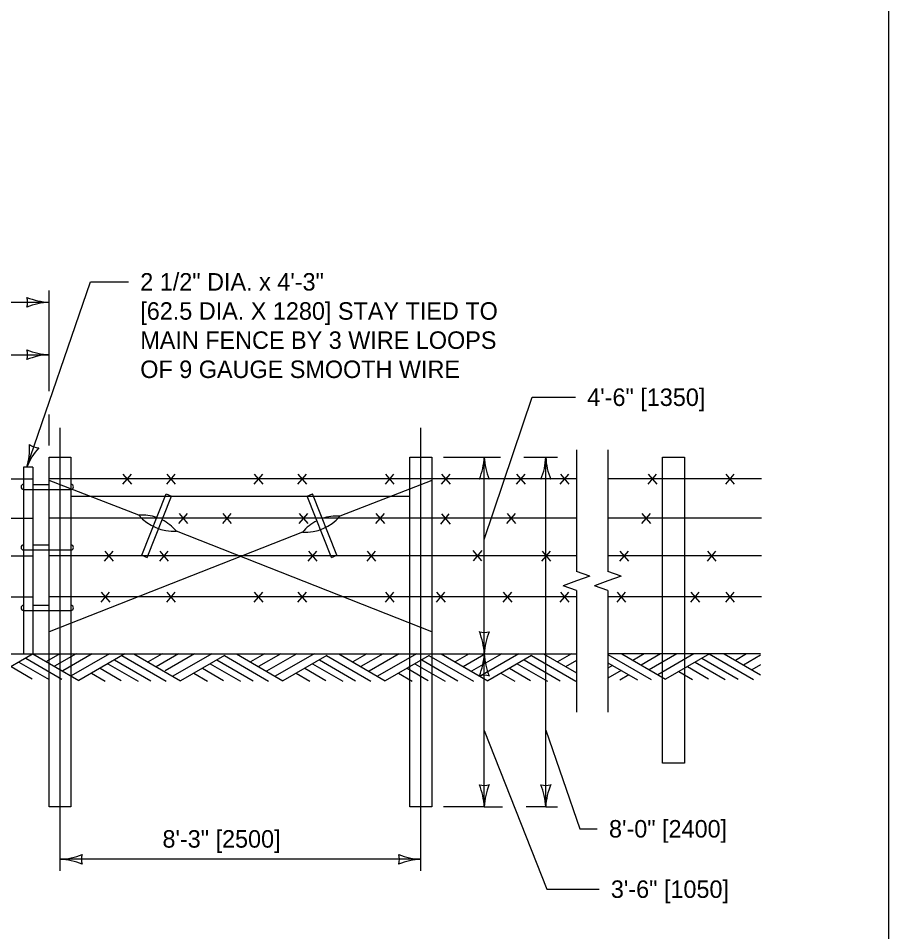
# Model space of a CAD drawing. Extents: x 49991.4 to 50021, y 49987.6 to 50011.4.
# Drawn here: x 50005.629 to 50008.615, y 50005.124 to 50008.258 of the extents above; entities that cross this region are included whole.
import ezdxf

# ---------------------------------------------------------------- set-up
doc = ezdxf.new("R2010")
doc.units = 0
for name, color, linetype in [('Level 1', 7, 'Continuous'), ('Level 2', 7, 'Continuous'), ('Level 3', 7, 'Continuous'), ('Level 4', 7, 'Continuous'), ('Level 5', 7, 'Continuous'), ('Level 6', 7, 'Continuous')]:
    doc.layers.add(name, color=color, linetype=linetype)

msp = doc.modelspace()

# ---------------------------------------------------------------- linework, layer by layer
at = {"layer": 'Level 1'}
for p, q in [((50005.7349, 50006.7523), (50005.8099, 50006.7523)), ((50005.7349, 50006.0773), (50005.7349, 50006.7523)), ((50005.8099, 50006.7523), (50005.8099, 50006.0773)), ((50006.9724, 50006.7523), (50007.0474, 50006.7523)), ((50006.9724, 50006.0773), (50006.9724, 50006.7523)), ((50007.0474, 50006.7523), (50007.0474, 50006.0773)), ((50007.8389, 50006.0773), (50007.8389, 50006.7523)), ((50007.8389, 50006.7523), (50007.9139, 50006.7523)), ((50007.9139, 50006.7523), (50007.9139, 50006.0773)), ((50005.6786, 50006.7176), (50005.6474, 50006.7176)), ((50005.6474, 50006.7176), (50005.6474, 50006.0776)), ((50005.6786, 50006.7176), (50005.6786, 50006.0776)), ((50005.9882, 50006.6592), (50006.0175, 50006.6939)), ((50006.0189, 50006.6592), (50005.9895, 50006.6939)), ((50006.1382, 50006.6592), (50006.1675, 50006.6939)), ((50006.1689, 50006.6592), (50006.1395, 50006.6939)), ((50006.4382, 50006.6592), (50006.4675, 50006.6939)), ((50006.4689, 50006.6592), (50006.4395, 50006.6939)), ((50006.5882, 50006.6592), (50006.6175, 50006.6939)), ((50006.6189, 50006.6592), (50006.5895, 50006.6939)), ((50006.8882, 50006.6592), (50006.9175, 50006.6939)), ((50006.9189, 50006.6592), (50006.8895, 50006.6939)), ((50007.081, 50006.6592), (50007.1103, 50006.6939)), ((50007.1117, 50006.6592), (50007.0823, 50006.6939)), ((50007.3382, 50006.6592), (50007.3675, 50006.6939)), ((50007.3689, 50006.6592), (50007.3395, 50006.6939)), ((50007.4882, 50006.6592), (50007.5175, 50006.6939)), ((50007.5189, 50006.6592), (50007.4895, 50006.6939)), ((50007.7892, 50006.6592), (50007.8185, 50006.6939)), ((50007.8199, 50006.6592), (50007.7905, 50006.6939)), ((50008.0555, 50006.6592), (50008.0848, 50006.6939)), ((50008.0862, 50006.6592), (50008.0568, 50006.6939)), ((50003.4298, 50006.6773), (50005.6786, 50006.6773)), ((50007.5434, 50006.6773), (50005.7349, 50006.6773)), ((50006.043, 50006.5531), (50005.7349, 50006.6718)), ((50006.9724, 50006.6773), (50005.8099, 50006.6773)), ((50007.0474, 50006.6721), (50006.7323, 50006.5496)), ((50008.1784, 50006.6773), (50007.6513, 50006.6773)), ((50005.6474, 50006.6411), (50005.8099, 50006.6411)), ((50005.6786, 50006.6587), (50005.7349, 50006.6587)), ((50006.9724, 50006.6173), (50005.8099, 50006.6173)), ((50006.0529, 50006.4157), (50006.1361, 50006.6257)), ((50006.0715, 50006.4083), (50006.1547, 50006.6183)), ((50006.1361, 50006.6257), (50006.1547, 50006.6183)), ((50006.6199, 50006.6183), (50006.6385, 50006.6257)), ((50006.7032, 50006.4083), (50006.6199, 50006.6183)), ((50006.7217, 50006.4157), (50006.6385, 50006.6257)), ((50003.4298, 50006.5423), (50005.6786, 50006.5423)), ((50007.5434, 50006.5423), (50005.7349, 50006.5423)), ((50006.1803, 50006.5242), (50006.2097, 50006.5589)), ((50006.211, 50006.5242), (50006.1817, 50006.5589)), ((50006.3303, 50006.5242), (50006.3597, 50006.5589)), ((50006.361, 50006.5242), (50006.3317, 50006.5589)), ((50006.5928, 50006.5242), (50006.6222, 50006.5589)), ((50006.6235, 50006.5242), (50006.5942, 50006.5589)), ((50006.8553, 50006.5242), (50006.8847, 50006.5589)), ((50006.886, 50006.5242), (50006.8567, 50006.5589)), ((50007.0782, 50006.5227), (50007.1076, 50006.5574)), ((50007.1114, 50006.5227), (50007.0821, 50006.5574)), ((50007.3053, 50006.5242), (50007.3347, 50006.5589)), ((50007.336, 50006.5242), (50007.3067, 50006.5589)), ((50008.1784, 50006.5423), (50007.6513, 50006.5423)), ((50007.7676, 50006.5242), (50007.797, 50006.5589)), ((50007.7983, 50006.5242), (50007.769, 50006.5589)), ((50006.6039, 50006.4945), (50005.7349, 50006.1523)), ((50007.0474, 50006.1523), (50006.1715, 50006.498)), ((50005.6786, 50006.4512), (50005.7349, 50006.4512)), ((50003.4298, 50006.4133), (50005.6786, 50006.4133)), ((50005.6474, 50006.4336), (50005.8099, 50006.4336)), ((50007.5434, 50006.4133), (50005.7349, 50006.4133)), ((50005.9253, 50006.3952), (50005.9547, 50006.4299)), ((50005.956, 50006.3952), (50005.9267, 50006.4299)), ((50006.0529, 50006.4157), (50006.0715, 50006.4083)), ((50006.1142, 50006.3952), (50006.1436, 50006.4299)), ((50006.1449, 50006.3952), (50006.1156, 50006.4299)), ((50006.6238, 50006.3952), (50006.6532, 50006.4299)), ((50006.6545, 50006.3952), (50006.6252, 50006.4299)), ((50006.7032, 50006.4083), (50006.7217, 50006.4157)), ((50006.8253, 50006.3952), (50006.8547, 50006.4299)), ((50006.856, 50006.3952), (50006.8267, 50006.4299)), ((50007.2189, 50006.3966), (50007.1896, 50006.4313)), ((50007.1907, 50006.3966), (50007.2201, 50006.4313)), ((50007.4253, 50006.3952), (50007.4547, 50006.4299)), ((50007.456, 50006.3952), (50007.4267, 50006.4299)), ((50008.1784, 50006.4133), (50007.6513, 50006.4133)), ((50007.6926, 50006.3952), (50007.722, 50006.4299)), ((50007.7233, 50006.3952), (50007.694, 50006.4299)), ((50007.9926, 50006.3952), (50008.022, 50006.4299)), ((50008.0233, 50006.3952), (50007.994, 50006.4299)), ((50005.9132, 50006.2542), (50005.9425, 50006.2889)), ((50005.9439, 50006.2542), (50005.9145, 50006.2889)), ((50006.1382, 50006.2542), (50006.1675, 50006.2889)), ((50006.1689, 50006.2542), (50006.1395, 50006.2889)), ((50006.4382, 50006.2542), (50006.4675, 50006.2889)), ((50006.4689, 50006.2542), (50006.4395, 50006.2889)), ((50006.5882, 50006.2542), (50006.6175, 50006.2889)), ((50006.6189, 50006.2542), (50006.5895, 50006.2889)), ((50006.8882, 50006.2542), (50006.9175, 50006.2889)), ((50006.9189, 50006.2542), (50006.8895, 50006.2889)), ((50007.0634, 50006.2542), (50007.0927, 50006.2889)), ((50007.0941, 50006.2542), (50007.0647, 50006.2889)), ((50007.2922, 50006.2542), (50007.3215, 50006.2889)), ((50007.3229, 50006.2542), (50007.2935, 50006.2889)), ((50007.4882, 50006.2542), (50007.5175, 50006.2889)), ((50007.5189, 50006.2542), (50007.4895, 50006.2889)), ((50007.6827, 50006.2542), (50007.712, 50006.2889)), ((50007.7134, 50006.2542), (50007.684, 50006.2889)), ((50007.9355, 50006.2542), (50007.9648, 50006.2889)), ((50007.9662, 50006.2542), (50007.9368, 50006.2889)), ((50008.0555, 50006.2542), (50008.0848, 50006.2889)), ((50008.0862, 50006.2542), (50008.0568, 50006.2889)), ((50003.4298, 50006.2723), (50005.6786, 50006.2723)), ((50007.5434, 50006.2723), (50005.7349, 50006.2723)), ((50008.1784, 50006.2723), (50007.6513, 50006.2723)), ((50005.6474, 50006.2261), (50005.8099, 50006.2261)), ((50005.6786, 50006.2437), (50005.7349, 50006.2437)), ((50003.3349, 50006.0773), (50007.5434, 50006.0773)), ((50005.6804, 50006.0773), (50005.53, 50005.9904)), ((50005.6476, 50006.0776), (50005.6786, 50006.0776)), ((50005.6796, 50006.0773), (50005.8372, 50005.9863)), ((50005.7715, 50006.0773), (50005.7255, 50006.0508)), ((50005.8275, 50006.0773), (50005.7535, 50006.0346)), ((50005.8828, 50006.0773), (50005.7821, 50006.0192)), ((50005.9418, 50006.0773), (50005.8107, 50006.0016)), ((50005.9948, 50006.0773), (50005.8372, 50005.9863)), ((50005.9849, 50006.0716), (50006.1367, 50005.9839)), ((50006.026, 50006.0773), (50006.1859, 50005.9849)), ((50006.1226, 50006.0773), (50006.0743, 50006.0494)), ((50006.1786, 50006.0773), (50006.1018, 50006.033)), ((50006.2339, 50006.0773), (50006.1332, 50006.0192)), ((50006.2929, 50006.0773), (50006.1595, 50006.0002)), ((50006.336, 50006.0716), (50006.1859, 50005.9849)), ((50006.336, 50006.0716), (50006.4878, 50005.9839)), ((50006.3771, 50006.0773), (50006.537, 50005.9849)), ((50006.4737, 50006.0773), (50006.4254, 50006.0494)), ((50006.5297, 50006.0773), (50006.4533, 50006.0333)), ((50006.585, 50006.0773), (50006.481, 50006.0173)), ((50006.644, 50006.0773), (50006.5106, 50006.0002)), ((50006.6875, 50006.0718), (50006.537, 50005.9849)), ((50006.6867, 50006.0718), (50006.8389, 50005.9839)), ((50006.7282, 50006.0773), (50006.8881, 50005.9849)), ((50006.8248, 50006.0773), (50006.7765, 50006.0494)), ((50006.8808, 50006.0773), (50006.8044, 50006.0333)), ((50006.9361, 50006.0773), (50006.8321, 50006.0173)), ((50006.9951, 50006.0773), (50006.8617, 50006.0002)), ((50007.0386, 50006.0718), (50006.8881, 50005.9849)), ((50007.0378, 50006.0718), (50007.19, 50005.9839)), ((50007.0793, 50006.0773), (50007.2392, 50005.9849)), ((50007.1759, 50006.0773), (50007.1275, 50006.0494)), ((50007.2319, 50006.0773), (50007.1555, 50006.0332)), ((50007.2872, 50006.0773), (50007.1832, 50006.0173)), ((50007.3462, 50006.0773), (50007.2128, 50006.0002)), ((50007.3897, 50006.0718), (50007.2392, 50005.9849)), ((50007.3889, 50006.0718), (50007.5411, 50005.9839)), ((50007.4304, 50006.0773), (50007.5434, 50006.012)), ((50007.527, 50006.0773), (50007.4786, 50006.0494)), ((50008.1746, 50006.0773), (50007.6513, 50006.0773)), ((50007.6513, 50006.0752), (50007.7999, 50005.9894)), ((50007.6987, 50006.0773), (50007.8492, 50005.9904)), ((50007.7762, 50006.0773), (50007.7375, 50006.0549)), ((50007.8323, 50006.0773), (50007.7654, 50006.0388)), ((50007.8875, 50006.0773), (50007.7931, 50006.0228)), ((50007.9466, 50006.0773), (50007.8227, 50006.0057)), ((50007.9996, 50006.0773), (50007.8492, 50005.9904)), ((50007.9988, 50006.0773), (50008.151, 50005.9894)), ((50008.0498, 50006.0773), (50008.1746, 50006.0052)), ((50008.1273, 50006.0773), (50008.0886, 50006.0549)), ((50008.1746, 50006.0722), (50008.1165, 50006.0388)), ((50005.631, 50006.0488), (50005.735, 50005.9887)), ((50005.6547, 50006.0624), (50005.779, 50005.9906)), ((50005.9359, 50006.0433), (50006.0399, 50005.9832)), ((50005.9596, 50006.0569), (50006.0839, 50005.9851)), ((50006.287, 50006.0433), (50006.391, 50005.9832)), ((50006.3107, 50006.0569), (50006.435, 50005.9851)), ((50006.6381, 50006.0433), (50006.7421, 50005.9832)), ((50006.6618, 50006.0569), (50006.7861, 50005.9851)), ((50006.9892, 50006.0433), (50007.0932, 50005.9832)), ((50007.0129, 50006.0569), (50007.1372, 50005.9851)), ((50007.3403, 50006.0433), (50007.4443, 50005.9832)), ((50007.364, 50006.0569), (50007.4883, 50005.9851)), ((50007.5434, 50006.0545), (50007.5066, 50006.0332)), ((50007.6513, 50006.0467), (50007.7528, 50005.9881)), ((50007.6671, 50006.0376), (50007.6513, 50006.0284)), ((50007.9502, 50006.0488), (50008.0542, 50005.9887)), ((50007.9739, 50006.0624), (50008.0982, 50005.9906)), ((50008.1746, 50006.0391), (50008.1453, 50006.0222)), ((50005.6047, 50006.0336), (50005.6769, 50005.9918)), ((50005.8803, 50006.0112), (50005.9274, 50005.9839)), ((50005.9096, 50006.0281), (50005.9818, 50005.9863)), ((50006.2314, 50006.0112), (50006.2785, 50005.9839)), ((50006.2607, 50006.0281), (50006.3329, 50005.9863)), ((50006.5825, 50006.0112), (50006.6296, 50005.9839)), ((50006.6118, 50006.0281), (50006.684, 50005.9863)), ((50006.9336, 50006.0112), (50006.9807, 50005.9839)), ((50006.9629, 50006.0281), (50007.0351, 50005.9863)), ((50007.2847, 50006.0112), (50007.3318, 50005.9839)), ((50007.314, 50006.0281), (50007.3862, 50005.9863)), ((50007.6967, 50006.0205), (50007.6513, 50005.9943)), ((50007.7231, 50006.0052), (50007.6924, 50005.9875)), ((50007.8946, 50006.0167), (50007.9417, 50005.9894)), ((50007.9239, 50006.0336), (50007.9961, 50005.9918))]:
    msp.add_line(p, q, dxfattribs=at)
msp.add_lwpolyline([(50008.6146, 50011.2628), (50000.3356, 50011.2628), (50000.3356, 50000.0624), (50008.6146, 50000.0624)], close=True, dxfattribs=at)
for centre, radius, start, end in [((50005.6474, 50006.6499), 0.0088, 90, 270), ((50005.8099, 50006.6499), 0.0088, 270, 90), ((50006.0527, 50006.3984), 0.155, 70.692, 93.5951), ((50006.1618, 50006.6528), 0.155, 220.0078, 273.5951), ((50006.0527, 50006.3984), 0.155, 40.0078, 63.2871), ((50006.6135, 50006.6492), 0.155, 266.4347, 320.0376), ((50006.7227, 50006.3949), 0.155, 86.4347, 109.12), ((50006.7227, 50006.3949), 0.155, 116.5245, 140.0376), ((50005.6474, 50006.4424), 0.0088, 90, 270), ((50005.8099, 50006.4424), 0.0088, 270, 90), ((50005.6474, 50006.2349), 0.0088, 90, 270), ((50005.8099, 50006.2349), 0.0088, 270, 90)]:
    msp.add_arc(centre, radius, start, end, dxfattribs=at)
at = {"layer": 'Level 3'}
for p, q in [((50005.6588, 50006.7176), (50005.8773, 50007.3536)), ((50005.8773, 50007.3536), (50006.0076, 50007.3536)), ((50005.7348, 50006.9788), (50005.7348, 50007.3236)), ((50003.3349, 50007.2836), (50005.7348, 50007.2836)), ((50004.9754, 50007.1036), (50005.7348, 50007.1036)), ((50005.7349, 50006.7923), (50005.7348, 50006.8989)), ((50007.0874, 50006.7523), (50007.2829, 50006.7523)), ((50007.2273, 50006.0773), (50007.2273, 50006.7523)), ((50007.3629, 50006.7524), (50007.4785, 50006.7523)), ((50007.4385, 50005.5523), (50007.4385, 50006.7523)), ((50007.2273, 50005.5523), (50007.2273, 50006.0773)), ((50007.2273, 50005.5523), (50007.0874, 50005.5523)), ((50007.2273, 50005.5523), (50007.2905, 50005.5523)), ((50007.4385, 50005.5523), (50007.3706, 50005.5523)), ((50007.4385, 50005.5523), (50007.4785, 50005.5523)), ((50007.0099, 50005.3723), (50005.7724, 50005.3723))]:
    msp.add_line(p, q, dxfattribs=at)
for points in [[(50007.2273, 50006.469), (50007.3922, 50006.9577), (50007.5405, 50006.9577)], [(50007.4385, 50005.8154), (50007.5556, 50005.477), (50007.6152, 50005.477)], [(50007.2273, 50005.8148), (50007.4417, 50005.2699), (50007.6216, 50005.2699), (50007.6216, 50005.2699)]]:
    msp.add_lwpolyline(points, dxfattribs=at)
for centre, radius, start, end in [((50005.744, 50007.5057), 0.2223, 247.456, 267.6395), ((50005.6066, 50007.2836), 0.0548, 342.1388, 17.8612), ((50005.7463, 50007.0509), 0.233, 92.8273, 112.0772), ((50005.744, 50007.3257), 0.2223, 247.456, 267.6395), ((50005.6066, 50007.1036), 0.0548, 342.1388, 17.8612), ((50005.7463, 50006.8709), 0.233, 92.8273, 112.0772), ((50005.435, 50006.7823), 0.233, 343.87, 3.1198), ((50005.7005, 50006.8389), 0.0548, 233.1815, 268.9038), ((50005.8659, 50006.6368), 0.2223, 138.4987, 158.6822), ((50007.0052, 50006.7615), 0.2223, 337.456, 357.6395), ((50007.46, 50006.7638), 0.233, 182.8273, 202.0772), ((50007.2164, 50006.7615), 0.2223, 337.456, 357.6395), ((50007.6712, 50006.7638), 0.233, 182.8273, 202.0772), ((50007.2273, 50006.6241), 0.0548, 72.1388, 107.8612), ((50007.4385, 50006.6241), 0.0548, 72.1388, 107.8612), ((50007.2273, 50006.2055), 0.0548, 252.1388, 287.8612), ((50006.9946, 50006.0658), 0.233, 2.8273, 22.0772), ((50007.4494, 50006.0681), 0.2223, 157.456, 177.6395), ((50007.0052, 50006.0865), 0.2223, 337.456, 357.6395), ((50007.46, 50006.0888), 0.233, 182.8273, 202.0772), ((50007.2273, 50005.9491), 0.0548, 72.1388, 107.8612), ((50007.2273, 50005.6805), 0.0548, 252.1388, 287.8612), ((50006.9946, 50005.5408), 0.233, 2.8273, 22.0772), ((50007.4494, 50005.5432), 0.2223, 157.456, 177.6395), ((50007.4385, 50005.6805), 0.0548, 252.1388, 287.8612), ((50007.2057, 50005.5408), 0.233, 2.8273, 22.0772), ((50007.6606, 50005.5432), 0.2223, 157.456, 177.6395), ((50005.7609, 50005.605), 0.233, 272.8273, 292.0772), ((50005.9006, 50005.3723), 0.0548, 162.1388, 197.8612), ((50007.0191, 50005.5944), 0.2223, 247.456, 267.6395), ((50006.8817, 50005.3723), 0.0548, 342.1388, 17.8612), ((50005.7632, 50005.1502), 0.2223, 67.456, 87.6395), ((50007.0214, 50005.1396), 0.233, 92.8273, 112.0772)]:
    msp.add_arc(centre, radius, start, end, dxfattribs=at)
at = {"layer": 'Level 4'}
for p, q in [((50005.7349, 50005.5523), (50005.7349, 50006.0773)), ((50005.8099, 50006.0773), (50005.8099, 50005.5523)), ((50006.9724, 50005.5523), (50006.9724, 50006.0773)), ((50007.0474, 50006.0773), (50007.0474, 50005.5523)), ((50007.8389, 50005.7023), (50007.8389, 50006.0773)), ((50007.9139, 50006.0773), (50007.9139, 50005.7023)), ((50007.9139, 50005.7023), (50007.8389, 50005.7023)), ((50005.8099, 50005.5523), (50005.7349, 50005.5523)), ((50007.0474, 50005.5523), (50006.9724, 50005.5523))]:
    msp.add_line(p, q, dxfattribs=at)
at = {"layer": 'Level 5'}
for p, q in [((50005.7724, 50005.3323), (50005.7724, 50006.8523)), ((50007.0099, 50005.3323), (50007.0099, 50006.8523))]:
    msp.add_line(p, q, dxfattribs=at)
at = {"layer": 'Level 6'}
for p, q in [((50007.5434, 50006.7773), (50007.5434, 50006.3597)), ((50007.6513, 50006.7773), (50007.6513, 50006.3597)), ((50007.5891, 50006.3435), (50007.5434, 50006.3597)), ((50007.697, 50006.3435), (50007.6513, 50006.3597)), ((50007.5434, 50006.3273), (50007.4977, 50006.3111)), ((50007.5891, 50006.3435), (50007.5434, 50006.3273)), ((50007.6513, 50006.3273), (50007.6056, 50006.3111)), ((50007.697, 50006.3435), (50007.6513, 50006.3273)), ((50007.5434, 50006.2949), (50007.4977, 50006.3111)), ((50007.5434, 50006.2949), (50007.5434, 50005.8773)), ((50007.6513, 50006.2949), (50007.6056, 50006.3111)), ((50007.6513, 50006.2949), (50007.6513, 50005.8773))]:
    msp.add_line(p, q, dxfattribs=at)

# ---------------------------------------------------------------- texts
at = {"layer": 'Level 2'}
for s, p in [('2 1/2" DIA. x 4\'-3" ', (50006.0476, 50007.3236)), ('[62.5 DIA. X 1280] STAY TIED TO', (50006.0476, 50007.2236)), ('MAIN FENCE BY 3 WIRE LOOPS', (50006.0476, 50007.1236)), ('OF 9 GAUGE SMOOTH WIRE', (50006.0476, 50007.0236)), ('4\'-6" [1350]', (50007.5805, 50006.9277)), ('8\'-0" [2400]', (50007.6552, 50005.447)), ('8\'-3" [2500]', (50006.1237, 50005.4123)), ('3\'-6" [1050]', (50007.6616, 50005.2399))]:
    msp.add_text(s, height=0.06, dxfattribs=at).set_placement(p)

doc.saveas('drawing.dxf')
